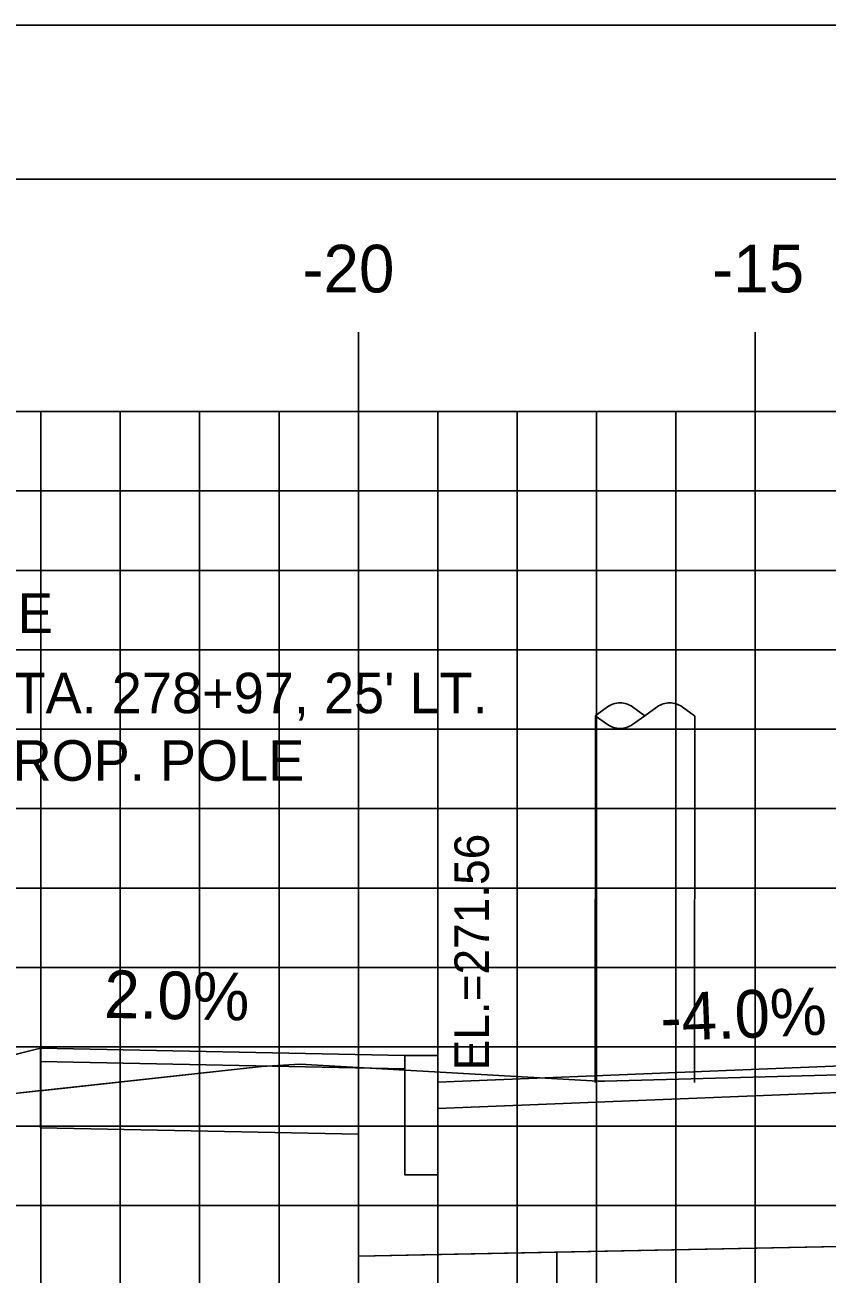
# Model space of a CAD drawing. Extents: x 854676 to 854846, y 366268 to 366378.
# Drawn here: x 854734.91 to 854745.01, y 366362.44 to 366378.18 of the extents above; entities that cross this region are included whole.
import ezdxf

# ---------------------------------------------------------------- set-up
doc = ezdxf.new("R2010")
doc.units = 0
for name, color, linetype in [('ANNOTATION', 7, 'Continuous'), ('BORDER', 7, 'Continuous'), ('D_Curb_Type1_Rt', 7, 'Continuous'), ('D_Curb_Type_1_Lt', 7, 'Continuous'), ('D_Roadway_Edge_Shoulder', 7, 'Continuous'), ('D_Roadway_FinishedGrade', 7, 'Continuous'), ('D_Roadway_Sidewalks_Paved', 7, 'Continuous'), ('D_Roadway_SubGrade', 7, 'Continuous'), ('D_Text_Monospaced', 7, 'Continuous'), ('D_Text_Standard', 7, 'Continuous'), ('D_Utilities_Text', 7, 'Continuous'), ('H_V ANNOTATION', 7, 'Continuous'), ('JUNK COM EXC', 7, 'Continuous'), ('JUNK FILL', 7, 'Continuous'), ('junk strct exc', 7, 'Continuous'), ('MAJOR', 7, 'Continuous'), ('MINOR', 7, 'Continuous'), ('PDRAIN', 7, 'Continuous'), ('PLOT BOUNDARY', 7, 'Continuous'), ('S_Roadway_Centerline', 7, 'Continuous'), ('S_Utilities_Pole_Power', 7, 'Continuous')]:
    doc.layers.add(name, color=color, linetype=linetype)

msp = doc.modelspace()

# ---------------------------------------------------------------- linework, layer by layer
at = {"layer": 'BORDER'}
msp.add_line((854844.107, 366376.236), (854684.107, 366376.236), dxfattribs=at)
at = {"layer": 'D_Curb_Type1_Rt'}
msp.add_line((854740.106, 366364.866), (854740.106, 366365.199), dxfattribs=at)
at = {"layer": 'D_Curb_Type_1_Lt'}
msp.add_lwpolyline([(854739.69, 366365.199), (854739.69, 366363.699), (854740.106, 366363.699), (854740.106, 366365.199)], close=True, dxfattribs=at)
at = {"layer": 'D_Roadway_Edge_Shoulder'}
msp.add_line((854740.106, 366364.866), (854740.106, 366364.533), dxfattribs=at)
msp.add_lwpolyline([(854740.106, 366364.866), (854748.106, 366365.186), (854759.106, 366365.296), (854770.106, 366365.076), (854778.106, 366364.755)], dxfattribs=at)
at = {"layer": 'D_Roadway_FinishedGrade'}
msp.add_line((854732.075, 366364.534), (854735.101, 366365.291), dxfattribs=at)
at = {"layer": 'D_Roadway_Sidewalks_Paved'}
msp.add_lwpolyline([(854735.101, 366365.291), (854739.69, 366365.199), (854739.69, 366365.032), (854735.101, 366365.124)], close=True, dxfattribs=at)
at = {"layer": 'D_Roadway_SubGrade'}
msp.add_line((854740.106, 366362.692), (854739.106, 366362.672), dxfattribs=at)
msp.add_lwpolyline([(854735.101, 366365.124), (854735.101, 366364.291), (854739.106, 366364.21), (854739.106, 366362.672)], dxfattribs=at)
msp.add_lwpolyline([(854748.106, 366364.852), (854740.106, 366364.532), (854740.106, 366362.692), (854748.106, 366362.852)], close=True, dxfattribs=at)
at = {"layer": 'JUNK COM EXC'}
for points in [[(854771.088, 366364.995), (854760.071, 366365.226), (854759.833, 366365.231), (854750.684, 366365.086), (854748.494, 366365.05), (854748.457, 366365.047), (854748.431, 366365.046), (854742.209, 366364.875), (854742.127, 366364.878), (854738.368, 366365.092), (854737.885, 366365.061), (854735.101, 366364.757)], [(854735.101, 366364.757), (854735.101, 366364.291), (854739.106, 366364.21), (854739.106, 366362.672), (854748.106, 366362.852), (854759.106, 366362.962), (854770.106, 366362.742), (854779.106, 366362.562)]]:
    msp.add_lwpolyline(points, dxfattribs=at)
at = {"layer": 'JUNK FILL'}
msp.add_lwpolyline([(854735.106, 366364.758), (854735.106, 366365.291), (854735.101, 366365.291), (854732.075, 366364.534), (854734.737, 366364.717)], close=True, dxfattribs=at)
at = {"layer": 'junk strct exc'}
msp.add_lwpolyline([(854739.106, 366362.672), (854739.106, 366358.789), (854741.606, 366358.789), (854741.606, 366362.722)], close=True, dxfattribs=at)
at = {"layer": 'MAJOR'}
for p, q in [((854739.106, 366374.311), (854739.106, 366373.309)), ((854744.106, 366374.311), (854744.106, 366373.309)), ((854689.106, 366373.309), (854829.106, 366373.309)), ((854689.106, 366373.309), (854829.106, 366373.309)), ((854739.106, 366353.309), (854739.106, 366373.309)), ((854744.106, 366353.309), (854744.106, 366373.309)), ((854689.106, 366368.309), (854829.106, 366368.309)), ((854689.106, 366363.309), (854829.106, 366363.309))]:
    msp.add_line(p, q, dxfattribs=at)
at = {"layer": 'MINOR'}
for p, q in [((854735.106, 366353.309), (854735.106, 366373.309)), ((854736.106, 366353.309), (854736.106, 366373.309)), ((854737.106, 366353.309), (854737.106, 366373.309)), ((854738.106, 366353.309), (854738.106, 366373.309)), ((854740.106, 366353.309), (854740.106, 366373.309)), ((854741.106, 366353.309), (854741.106, 366373.309)), ((854742.106, 366353.309), (854742.106, 366373.309)), ((854743.106, 366353.309), (854743.106, 366373.309)), ((854689.106, 366372.309), (854829.106, 366372.309)), ((854689.106, 366371.309), (854829.106, 366371.309)), ((854689.106, 366370.309), (854829.106, 366370.309)), ((854689.106, 366369.309), (854829.106, 366369.309)), ((854689.106, 366367.309), (854829.106, 366367.309)), ((854689.106, 366366.309), (854829.106, 366366.309)), ((854689.106, 366365.309), (854829.106, 366365.309)), ((854689.106, 366364.309), (854829.106, 366364.309))]:
    msp.add_line(p, q, dxfattribs=at)
at = {"layer": 'PDRAIN'}
msp.add_lwpolyline([(854739.106, 366362.672), (854739.106, 366358.789), (854741.606, 366358.789), (854741.606, 366362.722)], dxfattribs=at)
at = {"layer": 'PLOT BOUNDARY'}
msp.add_lwpolyline([(854676.013, 366268.177), (854846.013, 366268.177), (854846.013, 366378.177), (854676.013, 366378.177)], close=True, dxfattribs=at)
at = {"layer": 'S_Roadway_Centerline'}
msp.add_lwpolyline([(854696.367, 366363.291), (854702.494, 366363.706), (854707.878, 366363.872), (854728.577, 366364.293), (854734.737, 366364.717), (854737.885, 366365.061), (854738.368, 366365.092), (854742.127, 366364.878), (854742.209, 366364.875), (854748.431, 366365.046), (854748.457, 366365.047), (854748.494, 366365.05), (854750.684, 366365.086), (854759.833, 366365.231), (854760.071, 366365.226), (854771.088, 366364.995)], dxfattribs=at)
at = {"layer": 'S_Utilities_Pole_Power'}
for p, q in [((854742.091, 366369.479), (854742.247, 366369.59)), ((854742.091, 366364.86), (854742.094, 366369.479)), ((854742.247, 366369.368), (854742.091, 366369.479)), ((854742.559, 366369.59), (854742.716, 366369.479)), ((854742.716, 366369.479), (854742.559, 366369.368)), ((854742.872, 366369.59), (854742.716, 366369.479)), ((854743.341, 366369.479), (854743.184, 366369.59)), ((854743.341, 366364.86), (854743.344, 366369.479))]:
    msp.add_line(p, q, dxfattribs=at)
for centre, start, end in [((854742.403, 366369.369), 90, 125.2644), ((854742.403, 366369.369), 54.7356, 90), ((854743.028, 366369.369), 90, 125.2644), ((854743.028, 366369.369), 54.7356, 90), ((854742.403, 366369.59), 234.7356, 270), ((854742.403, 366369.59), 270, 305.2644)]:
    msp.add_arc(centre, 0.271, start, end, dxfattribs=at)

# ---------------------------------------------------------------- texts
at = {"layer": 'ANNOTATION'}
for s, rotation, p in [('2.0%', 358.8542, (854735.899, 366365.675)), ('-4.0%', 2.2906, (854742.922, 366365.379))]:
    msp.add_text(s, height=0.6, rotation=rotation, dxfattribs=at).set_placement(p)
at = {"layer": 'D_Text_Monospaced'}
msp.add_text('EXIST. 36" MAPLE', height=0.49998, dxfattribs=at).set_placement((854729.521, 366370.52))
at = {"layer": 'D_Text_Standard'}
msp.add_text(' EL.=271.56', height=0.4335, rotation=90, dxfattribs=at).set_placement((854740.75, 366364.85))
at = {"layer": 'D_Utilities_Text'}
for s, p in [("STA. 278+97, 25' LT.", (854734.293, 366369.51)), ('PROP. POLE', (854734.293, 366368.66))]:
    msp.add_text(s, height=0.51, dxfattribs=at).set_placement(p)
at = {"layer": 'H_V ANNOTATION'}
for s, p in [('-20', (854738.4, 366374.809)), ('-15', (854743.563, 366374.809))]:
    msp.add_text(s, height=0.6, dxfattribs=at).set_placement(p)

doc.saveas('drawing.dxf')
